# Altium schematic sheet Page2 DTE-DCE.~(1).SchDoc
size 431 x 279 mm; Date: Not shown in title block; ApprovedBy: Not shown in title block; CheckedBy: Not shown in title block; Author: Not shown in title block; CompanyName: Not shown in title block; Engineer: Not shown in title block; Organization: Not shown in title block; Address1: Not shown in title block; Address2: Not shown in title block; Address3: Not shown in title block; Address4: Not shown in title block; DocumentNumber: 1; Revision: Use project parameter SCH_Rev; SheetNumber: 2; SheetTotal: 5; PageSetup: Record=PageOptions|CenterHorizontal=True|CenterVertical=True|PrintScale=1.00|XCorrection=1.00|YCorrection=1.00|PrintKind=0|BorderSize=5000000|LeftOffset=0|BottomOffset=0|Orientation=2|PaperLength=1000|PaperWidth=1000|Scale=100|PaperSource=15|PrintQuality=600|MediaType=1|DitherType=10|PaperKind=Letter|PrintScaleMode=1
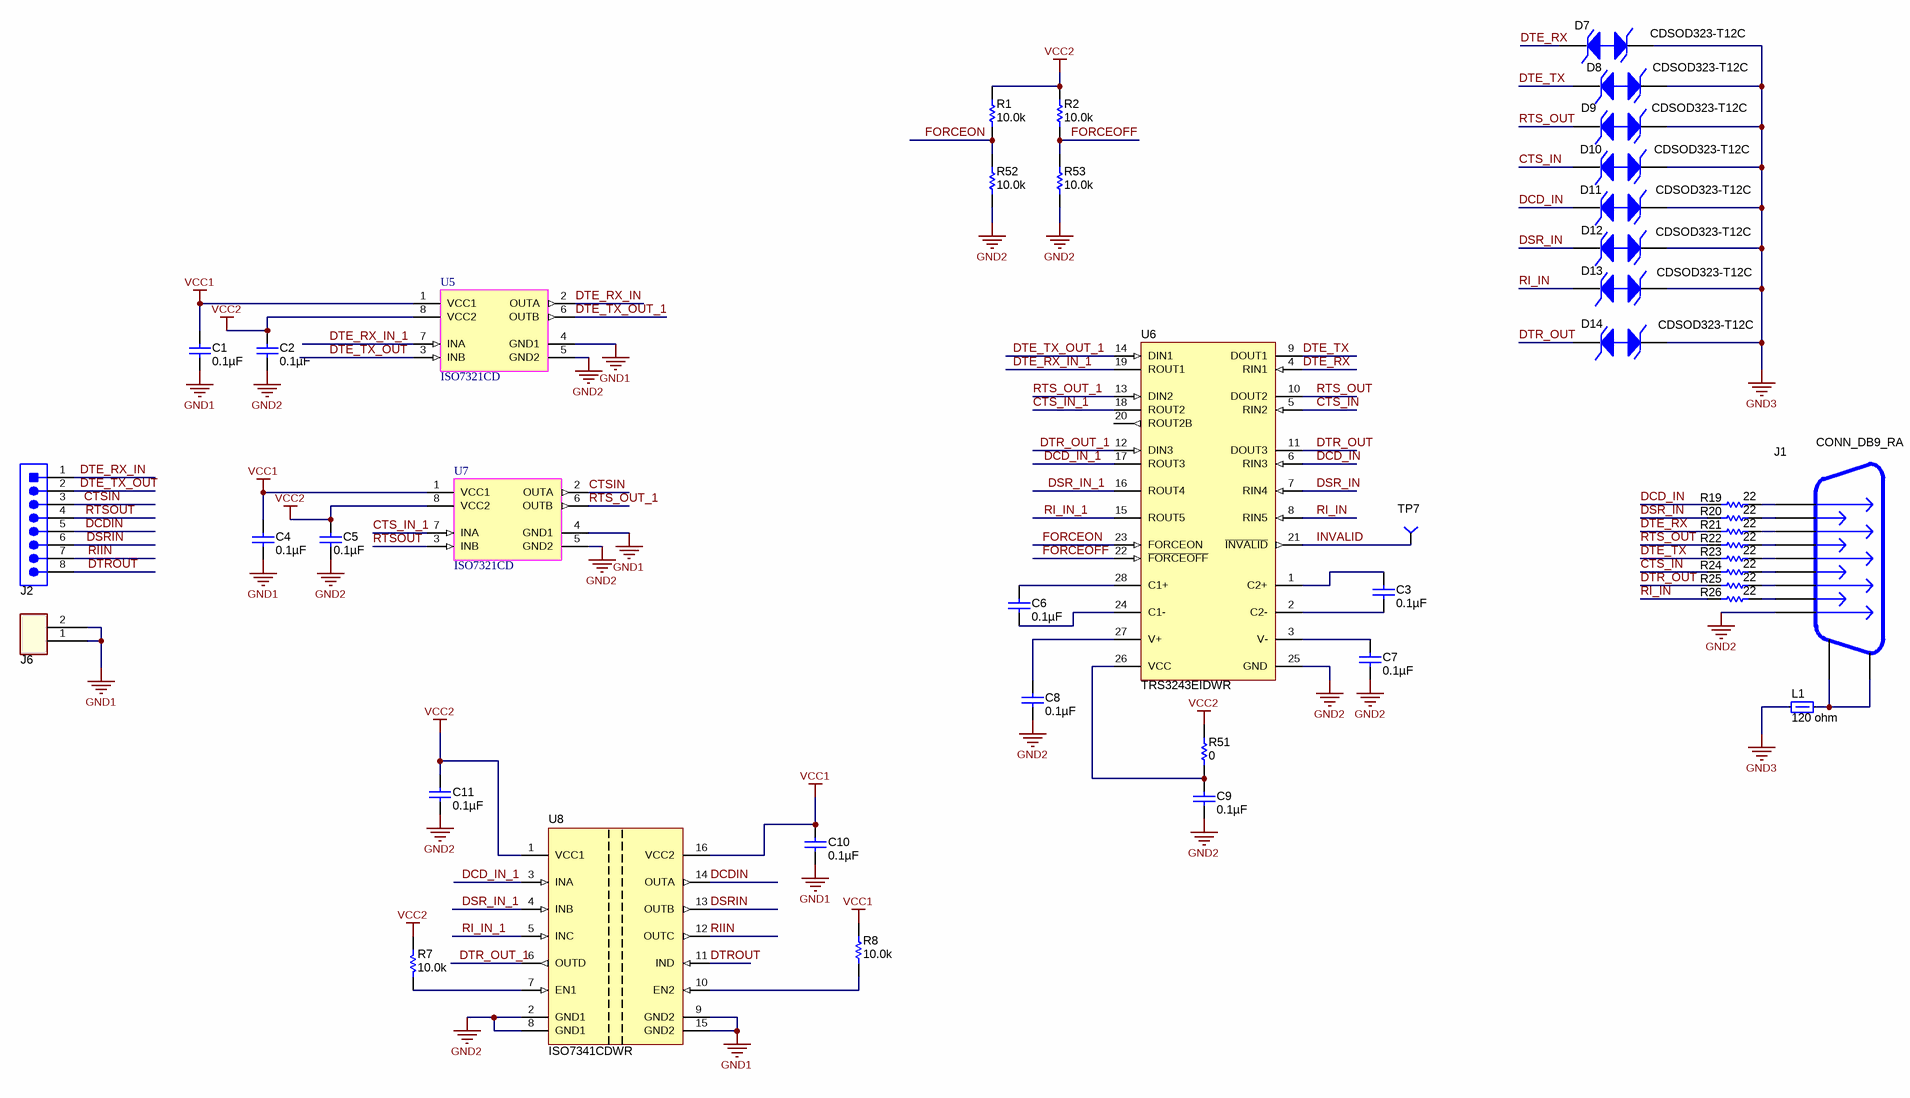
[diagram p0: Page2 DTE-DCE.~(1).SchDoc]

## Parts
C1  ValueDisplayed: 0.1µF  [0603]  (hidden comment: C0603C104K5RACTU)
C2  ValueDisplayed: 0.1µF  [0603]  (hidden comment: C0603C104K5RACTU)
C3  ValueDisplayed: 0.1µF  [0603]  (hidden comment: C0603C104K5RACTU)
C4  ValueDisplayed: 0.1µF  [0603]  (hidden comment: C0603C104K5RACTU)
C5  ValueDisplayed: 0.1µF  [0603]  (hidden comment: C0603C104K5RACTU)
C6  ValueDisplayed: 0.1µF  [0603]  (hidden comment: C0603C104K5RACTU)
C7  ValueDisplayed: 0.1µF  [0603]  (hidden comment: C0603C104K5RACTU)
C8  ValueDisplayed: 0.1µF  [0603]  (hidden comment: C0603C104K5RACTU)
C9  ValueDisplayed: 0.1µF  [0603]  (hidden comment: C0603C104K5RACTU)
C10  ValueDisplayed: 0.1µF  [0603]  (hidden comment: C0603C104K5RACTU)
C11  ValueDisplayed: 0.1µF  [0603]  (hidden comment: C0603C104K5RACTU)
D7  CDSOD323-T12C  [sod-323]
D8  CDSOD323-T12C  [sod-323]
D9  CDSOD323-T12C  [sod-323]
D10  CDSOD323-T12C  [sod-323]
D11  CDSOD323-T12C  [sod-323]
D12  CDSOD323-T12C  [sod-323]
D13  CDSOD323-T12C  [sod-323]
D14  CDSOD323-T12C  [sod-323]
J1  CONN_DB9_RA  [DB9_RA]
J2  1725711  [CONN_1725711]  (value not drawn)
J6  CON-OSTVN02A150  [CN2_MTB_P100_PD80_D1.1_S5.54X6.5_STACK]  (value not drawn)
L1  value 120 ohm  [0805_HV]  (hidden comment: BLM21AG121SN1D)
R1  value 10.0k  [0603]  (hidden comment: CRCW060310K0FKEA)
R2  value 10.0k  [0603]  (hidden comment: CRCW060310K0FKEA)
R7  value 10.0k  [0603]  (hidden comment: CRCW060310K0FKEA)
R8  value 10.0k  [0603]  (hidden comment: CRCW060310K0FKEA)
R19  ValueDisplayed: 22  [2512]  (hidden comment: RPC2512JT22R0)
R20  ValueDisplayed: 22  [2512]  (hidden comment: RPC2512JT22R0)
R21  ValueDisplayed: 22  [2512]  (hidden comment: RPC2512JT22R0)
R22  ValueDisplayed: 22  [2512]  (hidden comment: RPC2512JT22R0)
R23  ValueDisplayed: 22  [2512]  (hidden comment: RPC2512JT22R0)
R24  ValueDisplayed: 22  [2512]  (hidden comment: RPC2512JT22R0)
R25  ValueDisplayed: 22  [2512]  (hidden comment: RPC2512JT22R0)
R26  ValueDisplayed: 22  [2512]  (hidden comment: RPC2512JT22R0)
R51  ValueDisplayed: 0  [0603]  (hidden comment: CRCW06030000Z0EA)
R52  value 10.0k  [0603]  (hidden comment: CRCW060310K0FKEA)
R53  value 10.0k  [0603]  (hidden comment: CRCW060310K0FKEA)
TP7  TP-040_RND  [TP-040_RND]  (value not drawn)
U5  ISO7321CD
U6  TRS3243EIDWR  [DW0028A_N]
U7  ISO7321CD
U8  ISO7341CDWR  [DW0016B_HV]

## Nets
GND1: C1.2 C4.2 C10.2 J6.1 J6.2 U5.4(GND1) U7.4(GND1) U8.9(GND2) U8.15(GND2)
GND2: C2.2 C5.2 C7.2 C8.2 C9.2 C11.2 J1.5 R52.2 R53.1 U5.5(GND2) U6.25(GND) U7.5(GND2) U8.2(GND1) U8.8(GND1)
GND3: D7.2 D8.2 D9.2 D10.2 D11.2 D12.2 D13.2 D14.2 L1.2
VCC1: C1.1 C4.1 C10.1 R8.2 U5.1(VCC1) U7.1(VCC1) U8.16(VCC2)
VCC2: C2.1 C5.1 C11.1 R1.2 R2.2 R7.2 R51.1 U5.8(VCC2) U7.8(VCC2) U8.1(VCC1)
CTS_IN: D10.1 R24.1 U6.5(RIN2)
CTS_IN_1: U6.18(ROUT2) U7.7(INA)
CTSIN: J2.3 U7.2(OUTA)
DCD_IN: D11.1 R19.1 U6.6(RIN3)
DCD_IN_1: U6.17(ROUT3) U8.3(INA)
DCDIN: J2.5 U8.14(OUTA)
DSR_IN: D12.1 R20.1 U6.7(RIN4)
DSR_IN_1: U6.16(ROUT4) U8.4(INB)
DSRIN: J2.6 U8.13(OUTB)
DTE_RX: D7.1 R21.1 U6.4(RIN1)
DTE_RX_IN: J2.1 U5.2(OUTA)
DTE_RX_IN_1: U5.7(INA) U6.19(ROUT1)
DTE_TX: D8.1 R23.1 U6.9(DOUT1)
DTE_TX_OUT: J2.2 U5.3(INB)
DTE_TX_OUT_1: U5.6(OUTB) U6.14(DIN1)
DTR_OUT: D14.1 R25.1 U6.11(DOUT3)
DTR_OUT_1: U6.12(DIN3) U8.6(OUTD)
DTROUT: J2.8 U8.11(IND)
FORCEOFF: R2.1 R53.2 U6.22(~{FORCEOFF})
FORCEON: R1.1 R52.1 U6.23(FORCEON)
INVALID: TP7.1 U6.21(~{INVALID})
RI_IN: D13.1 R26.1 U6.8(RIN5)
RI_IN_1: U6.15(ROUT5) U8.5(INC)
RIIN: J2.7 U8.12(OUTC)
RTS_OUT: D9.1 R22.1 U6.10(DOUT2)
RTS_OUT_1: U6.13(DIN2) U7.6(OUTB)
RTSOUT: J2.4 U7.3(INB)
NetC3_1: C3.1 U6.1(C2+)
NetC3_2: C3.2 U6.2(C2-)
NetC6_1: C6.1 U6.28(C1+)
NetC6_2: C6.2 U6.24(C1-)
NetC7_1: C7.1 U6.3(V-)
NetC8_1: C8.1 U6.27(V+)
NetC9_1: C9.1 R51.2 U6.26(VCC)
NetJ1_1: J1.1 R19.2
NetJ1_2: J1.2 R21.2
NetJ1_3: J1.3 R23.2
NetJ1_4: J1.4 R25.2
NetJ1_6: J1.6 R20.2
NetJ1_7: J1.7 R22.2
NetJ1_8: J1.8 R24.2
NetJ1_9: J1.9 R26.2
NetJ1_10: J1.10(MOUNT1) J1.11(MOUNT2) L1.1
NetR7_1: R7.1 U8.7(EN1)
NetR8_1: R8.1 U8.10(EN2)

Not connected (* = marked no-connect by the designer): U6 20(ROUT2B)

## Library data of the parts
C1-C11 = C0603C104K5RACTU: CAP, CERM, 0.1uF, 50V, +/-10%, X7R, 0603; Manufacturer: Kemet; Polarized: N; CompType: Capacitor; U/M: EA; Cap_F: 0.0000001; Tolerance_%: 10; Value1: Unknown; VDC_V: 50; TaMin_C: -55; TaMax_C: 125
D7-D14 = CDSOD323-T15SC: Diode, TVS, ARRAY, 19V, SOD323; Manufacturer: Bourns Inc.; Value: 19
J1 = CONN_DB9_RA: Connector, 9-pin D, Right Angle, Male; Manufacturer: AMP; PartNumber: 747250-4; area: 1.021 inch; Value: 747250-4
J2 = 1725711: Terminal Block, 8x1, 2.54 mm, TH; Manufacturer: Phoenix Contact; SymbolCreator: a0411947; U/M: EA
J6 = CON-OSTVN02A150: CONN TERM BLOCK 2.54MM 2POS PCB; Manufacturer: On Shore Technology Inc; SymbolCreator: x0120606; CompType: Terminal Block
L1 = BLM21AG121SN1D: Ferrite Bead, 120 ohm @ 100 MHz, 0.8 A, 0805; Manufacturer: MuRata; Imax_A: 0.8; DCR_ohm: 0.1; Value1: 0.1 ohm; Value2: 0.8A; ZTyp@100MHz_Ohm: 120
R1 R2 R7 R8 R52 R53 = CRCW060310K0FKEA: RES, 10.0k ohm, 1%, 0.1W, 0603; Manufacturer: Vishay-Dale; CompType: Resistor; Res_ohm: 10000; Value_Code: 10k0; Tolerance_%: 1; Power_W: 0.1; VDC_V: 75; TempCo: 100 ppm/C; EIA_Code: E96; U/M: EA
R19-R26 = CRCW251210R0FKEG: RES SMD 22 OHM 5% 1.5W 2512; Manufacturer: Vishay-Dale; CompType: Resistor; Value: 10.0; Res_ohm: 10; Value_Code: 10R0; Tolerance_%: 1; Value1: 1%; Value2: 1W; VDC_V: 500; TempCo: 100 ppm/C; EIA_Code: E96; U/M: EA
R51 = CRCW06030000Z0EA: RES, 0, 5%, 0.1 W, 0603; Manufacturer: Vishay-Dale; CompType: Resistor; Value: 0; Value_Code: 0000; Tolerance_%: 5; Power_W: 0.1; Value2: 0.1W; VDC_V: 75; TempCo: 200 ppm/C; EIA_Code: E24; U/M: EA
TP7 = TP-040_RND: Test Point, O.040 Hole; Manufacturer: STD; Value: STD
U5 U7 = ISO7321CD: IC, ISOLATOR DGTL 2CH 1/1, SOIC-8, ROHS; Manufacturer: TEXAS INSTRUMENTS; CompType: ISOLATOR IC; SymbolCreator: x0199378
U6 = TRS3243EIDWR: 3-V to 5.5-V Multichannel RS-232 Line Driver / Receiver with ±15-kV IEC ESD Protection, -40 to 85 degC, 28-Pin SOIC (DW), Green (RoHS & no Sb/Br); Manufacturer: Texas Instruments; Alternate Manufacturer: None; Alternate PartNumber: Equivalent; Drivers Per Package: 3; Receivers Per Package: 5; Supply Voltage(s)(V): 3.3 or 5.0; ESD HBM(kV): +/-15; ICC(Max)(mA): 1; Single Supply: TRUE
U8 = ISO7341CDWR: Robust EMC, Low Power, Quad-Channel Digital Isolators, DW0016B; Manufacturer: Texas Instruments; SymbolCreator: Altium; CompType: IC; U/M: EA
